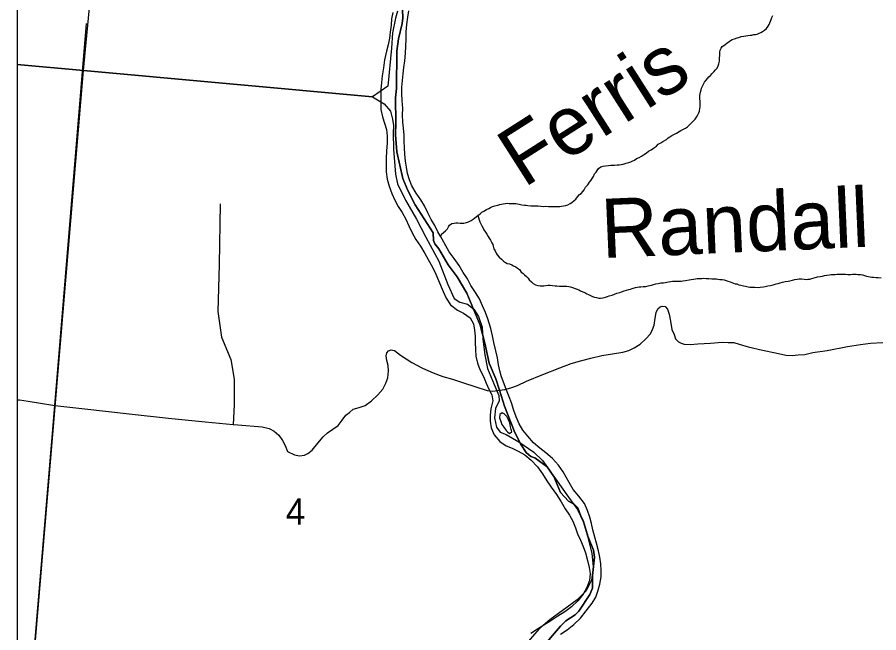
# Model space of a CAD drawing. Extents: x 0.4 to 34.4, y -2.1 to 19.9.
# Drawn here: x 3 to 4.379, y 12.684 to 13.669 of the extents above; entities that cross this region are included whole.
import ezdxf

# ---------------------------------------------------------------- set-up
doc = ezdxf.new("R2010")
doc.units = 0
for name, color, linetype in [('GM_X_County', 7, 'Continuous'), ('GM_X_Major_River', 7, 'Continuous'), ('GM_X_Minor_River', 7, 'Continuous'), ('GM_X_Minor_River_Text', 7, 'Continuous'), ('GM_X_Section', 7, 'Continuous'), ('GM_X_Section_Text', 7, 'Continuous'), ('GM_X_State_Route', 7, 'Continuous'), ('GM_X_Township', 7, 'Continuous'), ('GM_X_Township_Road', 7, 'Continuous'), ('GM_X_Township_ROW', 7, 'Continuous'), ('SH_Data', 7, 'Continuous')]:
    doc.layers.add(name, color=color, linetype=linetype)

msp = doc.modelspace()

# ---------------------------------------------------------------- linework, layer by layer
at = {"layer": 'GM_X_County'}
msp.add_lwpolyline([(9.8001, 15.3423), (9.8001, 18.8357), (3.0001, 18.8357), (3.0001, 12.0357), (9.5074, 12.0357)], dxfattribs=at)
at = {"layer": 'GM_X_Major_River'}
for points in [[(3.601, 13.6769), (3.599, 13.6667), (3.5984, 13.6565), (3.5971, 13.6455), (3.5958, 13.6357), (3.5938, 13.6251), (3.591, 13.6149), (3.5877, 13.6013), (3.586, 13.5881), (3.5843, 13.5756), (3.583, 13.565), (3.582, 13.5536), (3.5818, 13.5415), (3.5817, 13.5316), (3.5819, 13.5214), (3.5844, 13.51), (3.588, 13.4997), (3.5909, 13.4894), (3.5923, 13.4787), (3.5921, 13.4677), (3.5911, 13.4556), (3.5906, 13.4431), (3.5904, 13.4333), (3.5906, 13.4219), (3.5923, 13.4101), (3.5952, 13.3987), (3.5996, 13.3872), (3.6043, 13.3765), (3.6099, 13.3666), (3.6162, 13.357), (3.6217, 13.3463), (3.6268, 13.3352), (3.6324, 13.3234), (3.6379, 13.3134), (3.6453, 13.3031), (3.6523, 13.2912), (3.6579, 13.2816), (3.6645, 13.2694), (3.6697, 13.2583), (3.6744, 13.248), (3.6818, 13.2301), (3.6865, 13.2194), (3.6932, 13.2087), (3.7045, 13.2005), (3.7142, 13.1954), (3.7248, 13.1881), (3.7303, 13.1785), (3.732, 13.1682), (3.733, 13.1587), (3.7329, 13.1485), (3.7335, 13.1375), (3.7341, 13.1269), (3.7365, 13.1155), (3.7405, 13.1052), (3.7461, 13.0941), (3.7505, 13.0838)], [(3.6778, 13.3179), (3.673, 13.3258), (3.6682, 13.3357), (3.6627, 13.3453), (3.6572, 13.3564), (3.6516, 13.3675), (3.6461, 13.377), (3.6383, 13.3878), (3.6313, 13.3992), (3.628, 13.4092), (3.6247, 13.4194), (3.623, 13.4293), (3.6212, 13.4388), (3.6203, 13.4499), (3.6197, 13.4601), (3.6195, 13.4707), (3.6192, 13.4806), (3.6183, 13.4916), (3.6173, 13.5015), (3.6167, 13.5129), (3.6169, 13.5235), (3.6163, 13.536), (3.6157, 13.547), (3.6155, 13.5573), (3.6168, 13.5679), (3.6177, 13.5788), (3.619, 13.5891), (3.6203, 13.5997), (3.6213, 13.6118), (3.6218, 13.6228), (3.6224, 13.6345), (3.6226, 13.6459), (3.6235, 13.6576), (3.6252, 13.6694), (3.6269, 13.6796)], [(3.8694, 12.6815), (3.8802, 12.6889), (3.8906, 12.6971), (3.9014, 12.7075), (3.9106, 12.7191), (3.9199, 12.7311), (3.9258, 12.7409), (3.9294, 12.7507), (3.9322, 12.7616), (3.9343, 12.7737), (3.9344, 12.7836), (3.9338, 12.7942), (3.9325, 12.8049), (3.9304, 12.8151), (3.9268, 12.8273), (3.9243, 12.8372), (3.9214, 12.8486), (3.9189, 12.8589), (3.9164, 12.8692), (3.9128, 12.8799), (3.9076, 12.8909), (3.8987, 12.9025), (3.8898, 12.9132), (3.8831, 12.9243), (3.8739, 12.9415), (3.8661, 12.9523), (3.8567, 12.9627), (3.8459, 12.9719), (3.8361, 12.9797), (3.8264, 12.9882), (3.8171, 12.9985), (3.8093, 13.0085), (3.8033, 13.0185), (3.7986, 13.0295), (3.7949, 13.0398), (3.791, 13.052), (3.7873, 13.0616), (3.7829, 13.0726), (3.7793, 13.0826), (3.7749, 13.0936), (3.7724, 13.1031), (3.7703, 13.1127), (3.7685, 13.1241), (3.7661, 13.1355), (3.7629, 13.1484), (3.7604, 13.1591), (3.7579, 13.1713), (3.7532, 13.1865), (3.7492, 13.1968), (3.7448, 13.2075), (3.7397, 13.2186), (3.7334, 13.2289), (3.7259, 13.24), (3.7204, 13.2503), (3.7137, 13.2607), (3.7075, 13.2718), (3.6993, 13.2833), (3.6911, 13.294), (3.6859, 13.3036), (3.68, 13.3143), (3.6778, 13.3179)], [(3.7505, 13.0838), (3.7549, 13.0742), (3.7593, 13.0647), (3.7614, 13.0552), (3.7582, 13.0427), (3.7569, 13.0325), (3.7571, 13.0226), (3.7584, 13.012), (3.7632, 13.0009), (3.7725, 12.9901), (3.7823, 12.9832), (3.7921, 12.9796), (3.8019, 12.9749), (3.8121, 12.9687), (3.8226, 12.9605), (3.8326, 12.9498), (3.8408, 12.9386), (3.8475, 12.9272), (3.8545, 12.9168), (3.8631, 12.9053), (3.8705, 12.8934), (3.8771, 12.8823), (3.8838, 12.872), (3.889, 12.8624), (3.8934, 12.8517), (3.8966, 12.8422), (3.9014, 12.8323), (3.9058, 12.822), (3.9094, 12.8117), (3.9127, 12.7999), (3.9151, 12.7884), (3.9169, 12.7789), (3.916, 12.7679), (3.9116, 12.7566), (3.9057, 12.7457), (3.8972, 12.7353), (3.8868, 12.7256), (3.8761, 12.7174), (3.8653, 12.7107), (3.8538, 12.7029), (3.8427, 12.6959), (3.8324, 12.6896), (3.822, 12.6826)], [(3.7763, 13.0363), (3.7721, 13.0334), (3.772, 13.0281), (3.7738, 13.0223), (3.7756, 13.0174), (3.779, 13.0132), (3.7823, 13.0078)], [(3.7823, 13.0078), (3.7845, 13.0055), (3.7879, 13.0028), (3.7917, 13.0054), (3.7907, 13.0092), (3.7896, 13.0134), (3.7886, 13.0202), (3.7864, 13.0248), (3.7838, 13.0302), (3.7793, 13.0344), (3.7763, 13.0363)]]:
    msp.add_lwpolyline(points, dxfattribs=at)
at = {"layer": 'GM_X_Minor_River'}
for points in [[(4.0144, 13.4571), (4.0183, 13.4596), (4.0229, 13.463), (4.0257, 13.466), (4.0299, 13.4682), (4.0334, 13.4704), (4.0388, 13.4737), (4.0415, 13.4763), (4.0446, 13.4778), (4.0477, 13.48), (4.0508, 13.4815), (4.055, 13.4837), (4.0593, 13.4863), (4.062, 13.4878), (4.0662, 13.49), (4.0693, 13.4918), (4.0724, 13.4937), (4.0751, 13.4963), (4.0786, 13.4996), (4.0818, 13.503), (4.0849, 13.5064), (4.0869, 13.5094), (4.0892, 13.5131), (4.0908, 13.5165), (4.0917, 13.5192), (4.0925, 13.523), (4.093, 13.5256), (4.0927, 13.5298), (4.0927, 13.5325), (4.0928, 13.5351), (4.0925, 13.5386), (4.0925, 13.5412), (4.0926, 13.5439), (4.0931, 13.5469), (4.0935, 13.5496), (4.0947, 13.553), (4.0952, 13.5556), (4.0968, 13.559), (4.0984, 13.5624), (4.1, 13.5654), (4.1023, 13.5684), (4.1047, 13.5711), (4.107, 13.5737), (4.1097, 13.5759), (4.1121, 13.5793), (4.1148, 13.5819), (4.1172, 13.5849), (4.1199, 13.5879), (4.1215, 13.5913), (4.1227, 13.5947), (4.1236, 13.5989), (4.124, 13.6023), (4.1241, 13.6049), (4.1242, 13.6076), (4.1242, 13.6107), (4.1243, 13.6133), (4.1248, 13.6167), (4.1267, 13.6197), (4.1279, 13.6224), (4.1322, 13.6253), (4.1361, 13.6283), (4.1388, 13.6302), (4.1415, 13.632), (4.1442, 13.6339), (4.148, 13.6349), (4.1519, 13.6364), (4.1546, 13.6371), (4.1584, 13.6386), (4.1626, 13.6392), (4.1661, 13.6396), (4.1691, 13.6399), (4.1729, 13.6406), (4.1756, 13.6409), (4.1787, 13.6416), (4.1814, 13.6419), (4.184, 13.6423), (4.1875, 13.6437), (4.1902, 13.6448), (4.1929, 13.6467), (4.1956, 13.6485), (4.1991, 13.6515), (4.2015, 13.6549), (4.2034, 13.6575), (4.2043, 13.6602), (4.2055, 13.6628), (4.2063, 13.6655), (4.2075, 13.6689), (4.2091, 13.6719)], [(3.6778, 13.3179), (3.6789, 13.322), (3.6824, 13.325), (3.6855, 13.3273), (3.6886, 13.3306), (3.6902, 13.3336), (3.6918, 13.3363), (3.6957, 13.3392), (3.6991, 13.3399), (3.7018, 13.3403), (3.7052, 13.3402), (3.709, 13.3398), (3.7121, 13.3397), (3.7147, 13.3397), (3.719, 13.3407), (3.7224, 13.3418), (3.7263, 13.344), (3.7298, 13.3462), (3.7325, 13.3481), (3.7371, 13.3518), (3.741, 13.3548), (3.7437, 13.3574), (3.7468, 13.3588), (3.7511, 13.3618), (3.7545, 13.3633), (3.7572, 13.3647), (3.7607, 13.3662), (3.7642, 13.3673), (3.7692, 13.3687), (3.7726, 13.3698), (3.7776, 13.3705), (3.7807, 13.3712), (3.7845, 13.3715), (3.7871, 13.3714), (3.7913, 13.3713), (3.7948, 13.3713), (3.7978, 13.3709), (3.8031, 13.37), (3.8077, 13.3691), (3.8118, 13.3683), (3.8145, 13.3683), (3.8172, 13.3682), (3.8221, 13.3674), (3.8259, 13.3673), (3.8294, 13.3672), (3.8336, 13.3672), (3.8381, 13.3667), (3.8419, 13.3666), (3.8461, 13.3669), (3.8503, 13.3665), (3.8541, 13.3664), (3.8579, 13.3663), (3.8617, 13.3663), (3.8652, 13.3666), (3.8682, 13.3665), (3.8709, 13.3669), (3.874, 13.3672), (3.8778, 13.3679), (3.8813, 13.3689), (3.8851, 13.3712), (3.8878, 13.3726), (3.8913, 13.376), (3.894, 13.3782), (3.8968, 13.3816), (3.8996, 13.3857), (3.9023, 13.3872), (3.905, 13.3902), (3.9073, 13.3932), (3.9093, 13.3973), (3.9129, 13.4011), (3.9156, 13.4052), (3.9184, 13.4086), (3.9203, 13.4112), (3.9223, 13.4146), (3.9239, 13.4184), (3.9263, 13.4214), (3.9279, 13.424), (3.9302, 13.4274), (3.9341, 13.4296), (3.9379, 13.4311), (3.9414, 13.4314), (3.946, 13.4321), (3.9498, 13.4324), (3.9528, 13.4327), (3.9559, 13.4326), (3.9601, 13.4329), (3.9631, 13.4329), (3.9666, 13.4336), (3.9697, 13.4343), (3.9743, 13.4357), (3.9785, 13.4368), (3.9819, 13.4379), (3.985, 13.4393), (3.9877, 13.4408), (3.9912, 13.443), (3.9951, 13.4449), (3.9989, 13.4471), (4.0024, 13.4493), (4.0063, 13.4519), (4.0105, 13.4548), (4.0144, 13.4571)], [(3.7371, 13.3518), (3.7403, 13.3418), (3.7422, 13.3384), (3.7436, 13.3353), (3.7458, 13.3315), (3.7469, 13.3288), (3.7495, 13.3253), (3.7513, 13.3222), (3.7535, 13.3184), (3.7554, 13.3157), (3.7576, 13.3122), (3.7594, 13.3084), (3.7609, 13.3057), (3.7619, 13.3026), (3.763, 13.2988), (3.7648, 13.2954), (3.7667, 13.2919), (3.7681, 13.2892), (3.7711, 13.2854), (3.7748, 13.2819), (3.7782, 13.2788), (3.7816, 13.2768), (3.7842, 13.2752), (3.788, 13.2744), (3.7914, 13.2728), (3.7944, 13.2712), (3.7982, 13.2696), (3.8008, 13.2677), (3.8038, 13.2654), (3.8064, 13.2615), (3.809, 13.2599), (3.812, 13.2572), (3.815, 13.2541), (3.8176, 13.2514), (3.8194, 13.2487), (3.8228, 13.246), (3.8258, 13.2433), (3.8292, 13.2409), (3.8333, 13.2397), (3.8368, 13.2393), (3.8398, 13.2392), (3.8429, 13.2395), (3.8459, 13.2399), (3.8498, 13.2402), (3.8528, 13.2405), (3.8566, 13.24), (3.8608, 13.2396), (3.8638, 13.2392), (3.8676, 13.2387), (3.8711, 13.2386), (3.8756, 13.2386), (3.8798, 13.2389), (3.8825, 13.2384), (3.8855, 13.2376), (3.8886, 13.2368), (3.8931, 13.2352), (3.8961, 13.234), (3.8988, 13.2328), (3.9014, 13.2316), (3.9052, 13.23), (3.9082, 13.2285), (3.9116, 13.2265), (3.9142, 13.2253), (3.9172, 13.2237), (3.9207, 13.2225), (3.9237, 13.2213), (3.9271, 13.2205), (3.9305, 13.2197), (3.9335, 13.2196), (3.9378, 13.2203), (3.9416, 13.2214), (3.9447, 13.2221), (3.9474, 13.2232), (3.952, 13.2246), (3.9558, 13.2261), (3.9593, 13.2275), (3.9643, 13.2289), (3.9669, 13.2297), (3.9712, 13.2311), (3.975, 13.2326), (3.9785, 13.2333), (3.9815, 13.234), (3.9842, 13.235), (3.9892, 13.2365), (3.9919, 13.2372), (3.9953, 13.2375), (3.998, 13.2378), (4.0015, 13.2382), (4.0057, 13.2385), (4.0095, 13.2392), (4.0148, 13.2402), (4.0183, 13.2413), (4.0218, 13.2424), (4.0256, 13.243), (4.0298, 13.2441), (4.034, 13.2444), (4.0367, 13.2447), (4.0394, 13.2451), (4.0424, 13.2458), (4.0462, 13.2465), (4.0489, 13.2468)], [(4.0489, 13.2468), (4.0527, 13.2467), (4.0562, 13.2467), (4.06, 13.2466), (4.0627, 13.2469), (4.0653, 13.2473), (4.0695, 13.2479), (4.0753, 13.249), (4.0787, 13.2497), (4.0822, 13.25), (4.0852, 13.2507), (4.0879, 13.251), (4.091, 13.251), (4.0955, 13.2513), (4.0982, 13.2516), (4.1024, 13.2511), (4.1066, 13.2511), (4.1115, 13.2506), (4.1157, 13.2505), (4.1188, 13.2505), (4.1214, 13.25), (4.1245, 13.2496), (4.1279, 13.2495), (4.1313, 13.2487), (4.1343, 13.2479), (4.1374, 13.2467), (4.1408, 13.2455), (4.1438, 13.2447), (4.1491, 13.2427), (4.1518, 13.2423), (4.1548, 13.2411), (4.1578, 13.2402), (4.162, 13.2394), (4.1654, 13.2386), (4.1696, 13.2377), (4.1726, 13.2373), (4.176, 13.2372), (4.1806, 13.2372), (4.1856, 13.2367), (4.189, 13.237), (4.194, 13.2377), (4.197, 13.2384), (4.2013, 13.2391), (4.2055, 13.2401), (4.2097, 13.2412), (4.2143, 13.2423), (4.2177, 13.2433), (4.2208, 13.244), (4.2246, 13.2451), (4.2289, 13.2462), (4.2335, 13.2468), (4.2365, 13.2476), (4.2407, 13.2486), (4.2446, 13.2493), (4.248, 13.25), (4.2511, 13.2503), (4.2549, 13.2503), (4.2595, 13.2502), (4.2625, 13.2497), (4.2652, 13.2501), (4.2686, 13.25), (4.2717, 13.2511), (4.2755, 13.2522), (4.2805, 13.2536), (4.2851, 13.2543), (4.2885, 13.255), (4.292, 13.2557), (4.2954, 13.2564), (4.2996, 13.2571), (4.3023, 13.2574), (4.3054, 13.2577), (4.3088, 13.2576), (4.3122, 13.258), (4.3153, 13.2579), (4.3187, 13.2582), (4.3222, 13.2582), (4.3252, 13.2581), (4.3294, 13.2576), (4.3332, 13.2576), (4.3366, 13.2579), (4.3397, 13.2578), (4.3424, 13.2578), (4.3454, 13.2577), (4.3492, 13.2573), (4.3526, 13.2568), (4.3557, 13.256), (4.3591, 13.2548), (4.3617, 13.2544), (4.3648, 13.2536), (4.3678, 13.2531), (4.3705, 13.2531), (4.3747, 13.2526), (4.3777, 13.2526), (4.3827, 13.2521)]]:
    msp.add_lwpolyline(points, dxfattribs=at)
at = {"layer": 'GM_X_Section'}
for p, q in [((3.0001, 14.5041), (3.0001, 13.5939)), ((3.0001, 13.5939), (3.0001, 12.5214))]:
    msp.add_line(p, q, dxfattribs=at)
for points in [[(3.0001, 13.5939), (3.106, 13.5839), (3.192, 14.4845), (3.0001, 14.5041)], [(3.6086, 13.679), (3.6054, 13.668), (3.6008, 13.6446), (3.5989, 13.6197), (3.5929, 13.5592), (3.5684, 13.5418), (3.106, 13.5839), (3.192, 14.4845)], [(3.0001, 12.5214), (3.0167, 12.5198), (3.106, 13.5839), (3.0001, 13.5939)], [(3.0167, 12.5198), (3.106, 13.5839), (3.5684, 13.5418), (3.5871, 13.5309), (3.5975, 13.519), (3.6007, 13.5064), (3.6024, 13.4962), (3.6015, 13.4844), (3.6021, 13.4583), (3.6056, 13.4181), (3.6088, 13.4029), (3.6212, 13.3766), (3.6388, 13.346), (3.6539, 13.3173), (3.6748, 13.2791), (3.6893, 13.2413), (3.6991, 13.2192), (3.7081, 13.2134), (3.7205, 13.2101), (3.731, 13.202), (3.738, 13.1905), (3.7441, 13.1733), (3.7453, 13.154), (3.7483, 13.129), (3.7525, 13.1069), (3.7634, 13.0814), (3.771, 13.0638), (3.7713, 13.0555), (3.7654, 13.0431), (3.7636, 13.0283), (3.7671, 13.0131), (3.7727, 13.0051), (3.7824, 13.0015), (3.8027, 12.9894), (3.8266, 12.9731), (3.8404, 12.96), (3.8615, 12.9305), (3.8822, 12.9009), (3.8966, 12.8814), (3.9057, 12.8623), (3.9122, 12.8406), (3.9193, 12.8113), (3.9219, 12.7893), (3.9189, 12.7681), (3.9106, 12.7513), (3.896, 12.7367), (3.8799, 12.7249), (3.8523, 12.7049), (3.835, 12.6897), (3.8145, 12.6662)]]:
    msp.add_lwpolyline(points, dxfattribs=at)
at = {"layer": 'GM_X_State_Route'}
msp.add_lwpolyline([(3.0001, 13.057), (3.0037, 13.0569), (3.0177, 13.0549), (3.034, 13.0521), (3.0604, 13.0476), (3.1085, 13.0422), (3.1792, 13.0343), (3.2424, 13.0276), (3.3007, 13.0217), (3.3458, 13.0174), (3.3533, 13.0166), (3.3922, 13.0136), (3.4032, 13.0108), (3.4115, 13.0066), (3.4186, 13.0001), (3.4246, 12.9917), (3.4287, 12.9837), (3.4327, 12.9742), (3.4437, 12.9688), (3.452, 12.9672), (3.4596, 12.9682), (3.4653, 12.9708), (3.4721, 12.9764), (3.481, 12.9873), (3.4898, 12.9975), (3.4967, 13.0042), (3.505, 13.0098), (3.5134, 13.0158), (3.5203, 13.0244), (3.5261, 13.0323), (3.5318, 13.0368), (3.5379, 13.0417), (3.5474, 13.0446), (3.5569, 13.0476), (3.5668, 13.0554), (3.5772, 13.0648), (3.5852, 13.0742), (3.5898, 13.0836), (3.593, 13.0923), (3.5942, 13.1025), (3.5935, 13.1116), (3.5917, 13.1196), (3.5903, 13.1272), (3.5915, 13.1321), (3.5941, 13.1354), (3.5983, 13.1369), (3.604, 13.1357), (3.6134, 13.1281), (3.6318, 13.1165), (3.6484, 13.1073), (3.6657, 13.0999), (3.6812, 13.0944), (3.6967, 13.0897), (3.7144, 13.0842), (3.7326, 13.078), (3.7522, 13.0717), (3.7605, 13.0709), (3.7689, 13.0719), (3.7717, 13.0723), (3.7802, 13.0733), (3.7901, 13.0763), (3.8004, 13.08), (3.8152, 13.0866), (3.8411, 13.0974), (3.8681, 13.1081), (3.8867, 13.1151), (3.9034, 13.1198), (3.9178, 13.1235), (3.9353, 13.1279), (3.9527, 13.1307), (3.969, 13.1332), (3.9789, 13.1361), (3.9873, 13.1402), (3.9968, 13.1462), (4.006, 13.1544), (4.0133, 13.1627), (4.0164, 13.1695), (4.0191, 13.1766), (4.0207, 13.1876), (4.0223, 13.1967), (4.025, 13.2027), (4.0288, 13.2057), (4.0319, 13.2068), (4.0368, 13.2064), (4.0405, 13.2018), (4.0435, 13.1938), (4.0457, 13.1828), (4.0478, 13.1695), (4.0511, 13.1612), (4.0537, 13.1547), (4.0582, 13.1497), (4.0627, 13.1478), (4.0673, 13.1462), (4.0771, 13.1454), (4.0892, 13.1464), (4.1093, 13.1477), (4.1279, 13.1494), (4.1377, 13.1489), (4.1468, 13.1485), (4.1551, 13.1461), (4.1698, 13.1418), (4.1925, 13.1366), (4.2133, 13.1319), (4.2299, 13.1283), (4.2401, 13.1278), (4.2496, 13.1289), (4.2602, 13.1295), (4.2731, 13.1324), (4.2963, 13.136), (4.3289, 13.1421), (4.3494, 13.1453), (4.3657, 13.1474), (4.385, 13.1487)], dxfattribs=at)
at = {"layer": 'GM_X_Township'}
msp.add_line((3.0001, 17.934), (3.0001, 12.5191), dxfattribs=at)
for points in [[(3.8377, 12.6576), (3.8696, 12.6947), (3.8777, 12.7032), (3.893, 12.7126), (3.8988, 12.7187), (3.9161, 12.7454), (3.9206, 12.7553), (3.9208, 12.7759), (3.9237, 12.8049), (3.922, 12.8162), (3.9133, 12.8386), (3.9059, 12.8638), (3.9019, 12.8706), (3.8974, 12.8841), (3.8916, 12.8895), (3.8823, 12.8946), (3.8695, 12.9086), (3.8589, 12.9339), (3.8483, 12.9497), (3.8281, 12.9638), (3.8222, 12.9662), (3.8146, 12.9727), (3.8052, 12.9863), (3.7951, 13.0074), (3.7798, 13.0465), (3.7717, 13.0723), (3.766, 13.0904), (3.7553, 13.1154), (3.7484, 13.1478), (3.741, 13.1763), (3.7195, 13.2275), (3.7039, 13.2538), (3.6896, 13.2731), (3.6748, 13.2986), (3.6682, 13.3068), (3.666, 13.3121), (3.6656, 13.3242), (3.637, 13.369), (3.6249, 13.3921), (3.6171, 13.4114), (3.6073, 13.454), (3.6055, 13.4812), (3.6061, 13.5007), (3.6053, 13.5401), (3.6068, 13.5554), (3.6078, 13.6151), (3.6101, 13.6348), (3.6161, 13.6592), (3.617, 13.6682), (3.616, 13.6948)], [(3.616, 13.6948), (3.617, 13.6682), (3.6161, 13.6592), (3.6101, 13.6348), (3.6078, 13.6151), (3.6068, 13.5554), (3.6053, 13.5401), (3.6061, 13.5007), (3.6055, 13.4812), (3.6073, 13.454), (3.6171, 13.4114), (3.6249, 13.3921), (3.637, 13.369), (3.6656, 13.3242), (3.666, 13.3121), (3.6682, 13.3068), (3.6748, 13.2986), (3.6896, 13.2731), (3.7039, 13.2538), (3.7195, 13.2275), (3.741, 13.1763), (3.7484, 13.1478), (3.7553, 13.1154), (3.766, 13.0904), (3.7717, 13.0723), (3.7798, 13.0465), (3.7951, 13.0074), (3.8052, 12.9863), (3.8146, 12.9727), (3.8222, 12.9662), (3.8281, 12.9638), (3.8483, 12.9497), (3.8589, 12.9339), (3.8695, 12.9086), (3.8823, 12.8946), (3.8916, 12.8895), (3.8974, 12.8841), (3.9019, 12.8706), (3.9059, 12.8638), (3.9133, 12.8386), (3.922, 12.8162), (3.9237, 12.8049), (3.9208, 12.7759), (3.9206, 12.7553), (3.9161, 12.7454), (3.8988, 12.7187), (3.893, 12.7126), (3.8777, 12.7032), (3.8696, 12.6947), (3.8377, 12.6576)]]:
    msp.add_lwpolyline(points, dxfattribs=at)
at = {"layer": 'GM_X_Township_Road'}
for points in [[(3.0604, 13.0476), (3.111, 13.6592)], [(3.0168, 12.527), (3.0604, 13.0476)]]:
    msp.add_lwpolyline(points, dxfattribs=at)
at = {"layer": 'GM_X_Township_ROW'}
msp.add_lwpolyline([(3.325, 13.3707), (3.3231, 13.2733), (3.3212, 13.1984), (3.3269, 13.1572), (3.3418, 13.1216), (3.3475, 13.0898), (3.3475, 13.0486), (3.3458, 13.0174)], dxfattribs=at)
at = {"layer": 'SH_Data'}
msp.add_line((3.0001, 18.8357), (3.0001, 12.0357), dxfattribs=at)

# ---------------------------------------------------------------- texts
at = {"layer": 'GM_X_Minor_River_Text'}
for s, rotation, p in [('Ferris', 32.5246, (3.8105, 13.3952)), ('Randall', 2.4627, (3.936, 13.2837))]:
    msp.add_text(s, height=0.0947, rotation=rotation, dxfattribs=at).set_placement(p)
at = {"layer": 'GM_X_Section_Text'}
msp.add_text('4', height=0.0419, rotation=0, dxfattribs=at).set_placement((3.4298, 12.8571))

doc.saveas('drawing.dxf')
